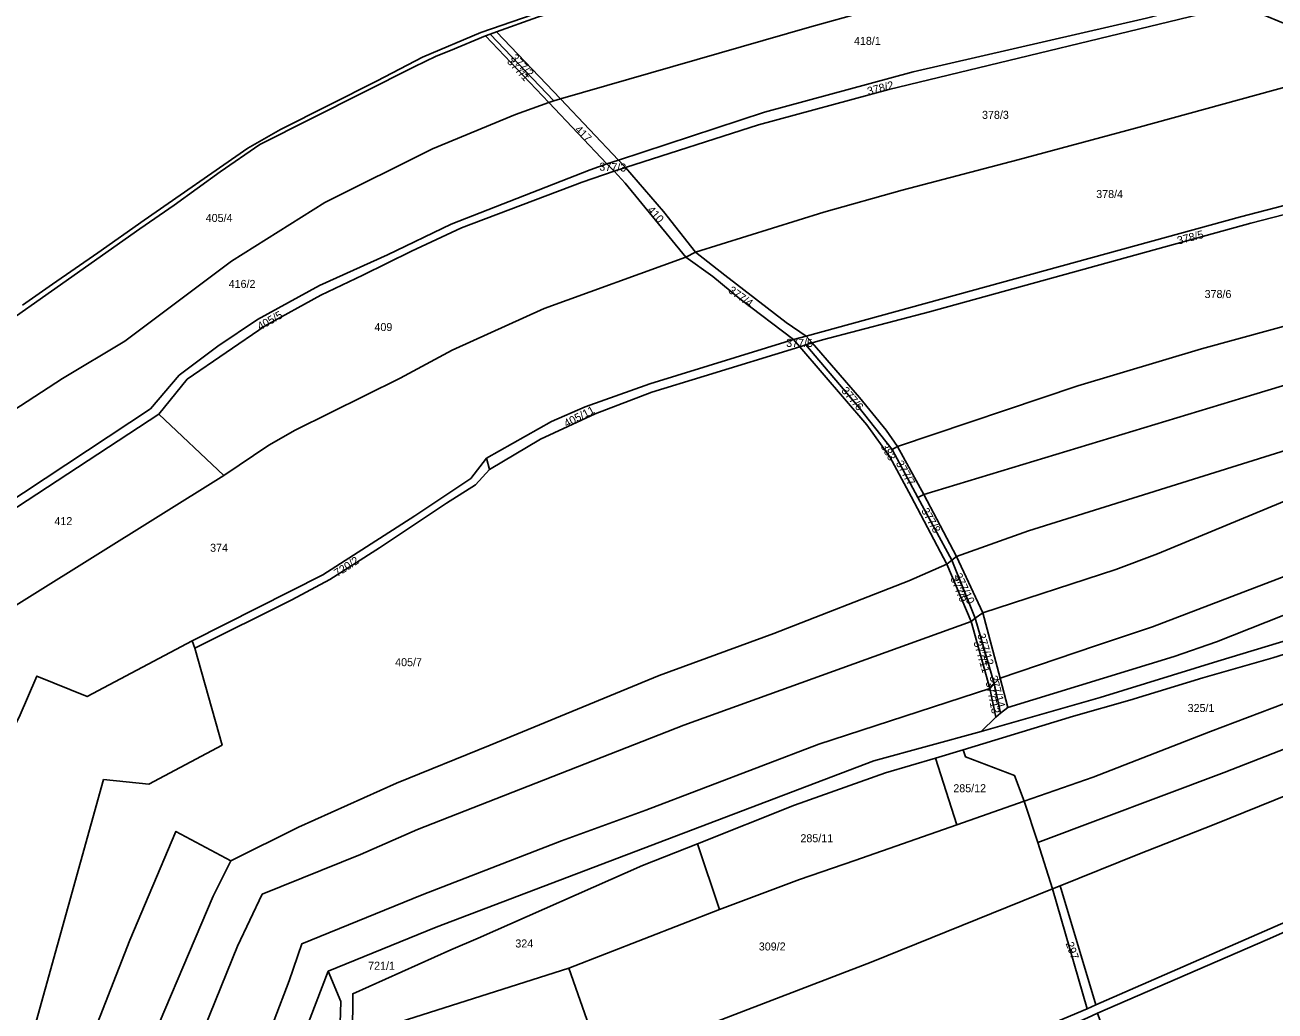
# Model space of a CAD drawing. Extents: x -629983 to -626385, y -1072828 to -1067897.
# Drawn here: x -629247.5 to -628779.1, y -1071013.1 to -1070643.4 of the extents above; entities that cross this region are included whole.
import ezdxf

# ---------------------------------------------------------------- set-up
doc = ezdxf.new("R2010")
doc.units = 0
for name, color, linetype in [('Parcela nároku', 7, 'Continuous'), ('Parcelní číslo', 7, 'Continuous'), ('Plocha PÚ', 7, 'Continuous'), ('Převzatý obvod_Ostrov', 7, 'Continuous')]:
    doc.layers.add(name, color=color, linetype=linetype)

msp = doc.modelspace()

# ---------------------------------------------------------------- linework, layer by layer
at = {"layer": 'Parcela nároku'}
for points in [[(-629013.24, -1070627.11), (-628985.46, -1070618.93), (-628958.27, -1070611.77), (-628927.76, -1070604.32), (-628897.63, -1070597.26), (-628879.21, -1070603.9), (-628844.64, -1070615.42), (-628910.36, -1070632.1), (-628953.49, -1070644.17), (-629046.78, -1070671.08), (-629070.87, -1070645.91), (-629055.42, -1070640.49)], [(-628910.36, -1070632.1), (-628844.64, -1070615.42), (-628818.36, -1070625.27), (-628798.59, -1070633.32), (-628827.25, -1070640.79), (-628914.69, -1070661.01), (-628970.38, -1070676.11), (-629025.16, -1070694.08), (-629046.78, -1070671.08), (-628953.49, -1070644.17)], [(-628798.59, -1070633.32), (-628792.54, -1070635.8), (-628923.84, -1070667.59), (-628972.69, -1070680.79), (-629022.54, -1070696.84), (-629025.16, -1070694.08), (-628970.38, -1070676.11), (-628914.69, -1070661.01), (-628827.25, -1070640.79)], [(-628972.69, -1070680.79), (-629022.54, -1070696.84), (-629008.29, -1070713.3), (-628996.19, -1070728.53), (-628948.21, -1070713.55), (-628918.79, -1070705.29), (-628875.5, -1070693.93), (-628831.39, -1070682.06), (-628740.78, -1070657.25), (-628741.75, -1070656.84), (-628792.54, -1070635.8), (-628923.84, -1070667.59)], [(-629101.65, -1070659.15), (-629093.4, -1070655.06), (-629088.1, -1070653), (-629074.99, -1070647.48), (-629051.24, -1070672.45), (-629063.68, -1070676.94), (-629094.76, -1070689.87), (-629135.11, -1070709.94), (-629170.12, -1070732.01), (-629210.07, -1070761.98), (-629233.47, -1070775.9), (-629265.09, -1070796.47), (-629274.72, -1070769.42), (-629271.88, -1070767.69), (-629254.96, -1070755.46), (-629237.53, -1070743.22), (-629204.46, -1070719.83), (-629191.61, -1070710.9), (-629174.38, -1070698.47), (-629159.54, -1070688.21)], [(-629074.99, -1070647.48), (-629073.14, -1070646.81), (-629049.29, -1070671.84), (-629051.24, -1070672.45)], [(-629046.78, -1070671.08), (-629070.87, -1070645.91), (-629073.14, -1070646.81), (-629049.29, -1070671.84)], [(-628996.19, -1070728.53), (-628948.21, -1070713.55), (-628918.79, -1070705.29), (-628875.5, -1070693.93), (-628831.39, -1070682.06), (-628740.78, -1070657.25), (-628678.53, -1070683.39), (-628715.57, -1070695.49), (-628792.01, -1070715.38), (-628954.79, -1070760.07), (-628962.29, -1070754.91), (-628985.21, -1070737.21)], [(-629025.16, -1070694.08), (-629046.78, -1070671.08), (-629049.29, -1070671.84), (-629051.24, -1070672.45), (-629029.46, -1070695.49)], [(-629094.76, -1070689.87), (-629063.68, -1070676.94), (-629051.24, -1070672.45), (-629029.46, -1070695.49), (-629035.66, -1070697.66), (-629087.84, -1070718.12), (-629111.67, -1070729.62), (-629137.1, -1070741.07), (-629160.38, -1070753.87), (-629175.26, -1070763.77), (-629189.77, -1070774.71), (-629200.54, -1070787.31), (-629255.88, -1070823.88), (-629265.09, -1070796.47), (-629233.47, -1070775.9), (-629210.07, -1070761.98), (-629170.12, -1070732.01), (-629135.11, -1070709.94)], [(-628954.79, -1070760.07), (-628792.01, -1070715.38), (-628715.57, -1070695.49), (-628678.53, -1070683.39), (-628673.98, -1070685.19), (-628698.34, -1070693.58), (-628726.09, -1070701.74), (-628788.2, -1070717.76), (-628908.59, -1070750.92), (-628948.65, -1070761.44), (-628952.57, -1070762.63)], [(-629022.54, -1070696.84), (-629025.16, -1070694.08), (-629029.46, -1070695.49), (-629026.7, -1070698.25)], [(-628682.68, -1070703.28), (-628657.28, -1070718.2), (-628720.79, -1070739.12), (-628766.88, -1070753.97), (-628806.63, -1070764.8), (-628852.98, -1070778.65), (-628920.59, -1070801.5), (-628924.83, -1070795.38), (-628934.8, -1070783.12), (-628952.57, -1070762.63), (-628948.65, -1070761.44), (-628908.59, -1070750.92), (-628788.2, -1070717.76), (-628726.09, -1070701.74), (-628698.34, -1070693.58)], [(-629186.68, -1070776.26), (-629197.39, -1070789.31), (-629173.04, -1070812.3), (-629156.13, -1070800.89), (-629146.31, -1070795.27), (-629106.88, -1070775.79), (-629087.44, -1070765.37), (-629052.94, -1070749.67), (-628999.82, -1070730.42), (-629022.57, -1070702.77), (-629026.7, -1070698.25), (-629038.74, -1070702.36), (-629083.96, -1070719.52), (-629102.68, -1070728.27), (-629120.87, -1070737.25), (-629136.63, -1070744.74), (-629157.54, -1070756.21)], [(-629008.29, -1070713.3), (-629022.54, -1070696.84), (-629026.7, -1070698.25), (-629022.57, -1070702.77), (-628999.82, -1070730.42), (-628996.19, -1070728.53)], [(-628852.98, -1070778.65), (-628806.63, -1070764.8), (-628766.88, -1070753.97), (-628720.79, -1070739.12), (-628657.28, -1070718.2), (-628621.8, -1070707.03), (-628585.37, -1070722.11), (-628616.48, -1070727.61), (-628668.51, -1070745.11), (-628714.67, -1070760.11), (-628786.96, -1070781.96), (-628910.71, -1070819.49), (-628920.59, -1070801.5)], [(-628558.83, -1070733.38), (-628585.37, -1070722.11), (-628616.48, -1070727.61), (-628668.51, -1070745.11), (-628714.67, -1070760.11), (-628786.96, -1070781.96), (-628910.71, -1070819.49), (-628898.44, -1070842.63), (-628871.48, -1070833.03), (-628737.85, -1070791.22), (-628704.59, -1070779.97), (-628653.5, -1070764.3), (-628624.58, -1070754.87), (-628588.5, -1070742.33), (-628543.99, -1070739.42)], [(-628999.82, -1070730.42), (-628996.19, -1070728.53), (-628985.21, -1070737.21), (-628962.29, -1070754.91), (-628954.79, -1070760.07), (-628959.48, -1070761.36), (-628979.67, -1070746.14), (-628989.79, -1070737.71)], [(-628871.48, -1070833.03), (-628898.44, -1070842.63), (-628888.62, -1070863.77), (-628838.74, -1070847.52), (-628823.11, -1070841.67), (-628766.75, -1070818.34), (-628648.3, -1070780.85), (-628589.41, -1070761.29), (-628565.93, -1070753.5), (-628536.65, -1070754.78), (-628495.21, -1070759.45), (-628543.99, -1070739.42), (-628588.5, -1070742.33), (-628624.58, -1070754.87), (-628653.5, -1070764.3), (-628704.59, -1070779.97), (-628737.85, -1070791.22)], [(-628952.57, -1070762.63), (-628954.79, -1070760.07), (-628959.48, -1070761.36), (-628957.18, -1070764.03), (-628954.9, -1070763.33)], [(-629050.26, -1070792.01), (-629037.59, -1070786.62), (-629013.39, -1070777.96), (-628959.48, -1070761.36), (-628957.18, -1070764.03), (-628992.94, -1070775.08), (-629012.6, -1070781.12), (-629033.87, -1070789.14), (-629054.29, -1070798.72), (-629073.48, -1070810.06), (-629074.59, -1070805.83)], [(-628935.34, -1070786.45), (-628922.49, -1070802.54), (-628912.94, -1070820.53), (-628900.23, -1070844.01), (-628902.04, -1070845.53), (-628915.37, -1070820.2), (-628923.37, -1070805.26), (-628932.03, -1070793.28), (-628957.18, -1070764.03), (-628954.9, -1070763.33)], [(-628924.83, -1070795.38), (-628934.8, -1070783.12), (-628952.57, -1070762.63), (-628954.9, -1070763.33), (-628935.34, -1070786.45), (-628922.49, -1070802.54), (-628920.59, -1070801.5)], [(-628648.3, -1070780.85), (-628589.41, -1070761.29), (-628572.41, -1070776.59), (-628625.53, -1070797.34), (-628734.06, -1070834.69), (-628769.79, -1070847.9), (-628824.99, -1070869.05), (-628846.39, -1070876.13), (-628882.09, -1070888.31), (-628888.62, -1070863.77), (-628838.74, -1070847.52), (-628823.11, -1070841.67), (-628766.75, -1070818.34)], [(-628889.23, -1070908.35), (-628883.68, -1070902.89), (-628881.9, -1070901.46), (-628879.17, -1070899.26), (-628816.86, -1070880.18), (-628801, -1070874.72), (-628763.76, -1070859.99), (-628742.31, -1070851.58), (-628735.56, -1070848.89), (-628720.22, -1070843.38), (-628564.53, -1070787.76), (-628561.86, -1070787.13), (-628551.1, -1070798.69), (-628536.84, -1070814.78), (-628534.91, -1070817.69), (-628557.5, -1070815.95), (-628585.88, -1070819.54), (-628600.88, -1070823.21), (-628678.75, -1070845.24), (-628688.76, -1070848.35), (-628744.82, -1070864.54), (-628759.63, -1070869.53), (-628800.48, -1070881.99), (-628844.62, -1070895.52)], [(-629197.39, -1070789.31), (-629173.04, -1070812.3), (-629270.52, -1070873.17), (-629303.76, -1070859.01)], [(-628910.71, -1070819.49), (-628920.59, -1070801.5), (-628922.49, -1070802.54), (-628912.94, -1070820.53)], [(-629074.59, -1070805.83), (-629073.48, -1070810.06), (-629078.63, -1070815.82), (-629089.62, -1070822.66), (-629114.65, -1070839.48), (-629133.27, -1070851.25), (-629147.58, -1070858.92), (-629183.91, -1070877.02), (-629184.9, -1070874.26), (-629135.89, -1070849.51), (-629101.48, -1070827.49), (-629080.5, -1070813.4)], [(-628898.44, -1070842.63), (-628910.71, -1070819.49), (-628912.94, -1070820.53), (-628900.23, -1070844.01)], [(-628720.36, -1070876.18), (-628702.04, -1070868.5), (-628660.34, -1070851.13), (-628626.54, -1070837.4), (-628606.71, -1070828.98), (-628587.61, -1070824.1), (-628581.08, -1070822.95), (-628556.43, -1070819.76), (-628536.2, -1070820.59), (-628538.6, -1070840.92), (-628545.57, -1070840.54), (-628558.89, -1070840.95), (-628576.35, -1070841.88), (-628601.81, -1070848.84), (-628703.02, -1070886.58), (-628798.08, -1070923.62), (-628868.01, -1070949.97), (-628873.03, -1070934.38), (-628847.27, -1070925.46), (-628803.26, -1070908.3), (-628775.51, -1070897.81), (-628747.43, -1070886.92)], [(-628854.59, -1070902.49), (-628833.46, -1070896.6), (-628806.15, -1070888.2), (-628779.89, -1070880.64), (-628727.93, -1070864.31), (-628710.91, -1070859.4), (-628691.48, -1070853.66), (-628662.34, -1070844.64), (-628606.71, -1070828.98), (-628626.54, -1070837.4), (-628660.34, -1070851.13), (-628702.04, -1070868.5), (-628720.36, -1070876.18), (-628747.43, -1070886.92), (-628775.51, -1070897.81), (-628803.26, -1070908.3), (-628847.27, -1070925.46), (-628873.03, -1070934.38), (-628876.66, -1070924.8), (-628895.1, -1070917.83), (-628895.99, -1070915.17)], [(-628900.23, -1070844.01), (-628891.44, -1070865.85), (-628892.9, -1070867.07), (-628902.04, -1070845.53)], [(-628888.62, -1070863.77), (-628898.44, -1070842.63), (-628900.23, -1070844.01), (-628891.44, -1070865.85)], [(-628891.44, -1070865.85), (-628888.62, -1070863.77), (-628882.09, -1070888.31), (-628884.28, -1070890.31)], [(-628891.44, -1070865.85), (-628884.28, -1070890.31), (-628885.99, -1070892.22), (-628892.9, -1070867.07)], [(-629243.05, -1070887.54), (-629249.69, -1070902.97), (-629259.41, -1070921.33), (-629274.51, -1070985.43), (-629284.16, -1071024.99), (-629291.51, -1071053.87), (-629257.36, -1071066.95), (-629218.07, -1070926.35), (-629201.11, -1070928.03), (-629173.63, -1070913.37), (-629183.91, -1070877.02), (-629184.9, -1070874.26), (-629224.26, -1070895.2)], [(-628884.28, -1070890.31), (-628885.99, -1070892.22), (-628883.68, -1070902.89), (-628881.9, -1070901.46)], [(-628879.17, -1070899.26), (-628882.09, -1070888.31), (-628884.28, -1070890.31), (-628881.9, -1070901.46)], [(-628876.66, -1070924.8), (-628873.03, -1070934.38), (-628898.34, -1070943.25), (-628906.36, -1070918.26), (-628895.99, -1070915.17), (-628895.1, -1070917.83)], [(-628906.36, -1070918.26), (-628898.34, -1070943.25), (-628936.49, -1070956.61), (-628957.25, -1070963.79), (-628987.23, -1070975.07), (-628995.45, -1070950.4), (-628959.11, -1070935.95), (-628925, -1070923.82)], [(-628873.03, -1070934.38), (-628898.34, -1070943.25), (-628936.49, -1070956.61), (-628957.25, -1070963.79), (-628987.23, -1070975.07), (-629043.77, -1070997.08), (-629031, -1071033.43), (-628930.4, -1070994.77), (-628862.45, -1070967.29), (-628868.01, -1070949.97)], [(-629294.85, -1071219.25), (-629303.85, -1071238.44), (-629324.52, -1071275.85), (-629358.36, -1071328.63), (-629347.5, -1071339.42), (-629338.48, -1071349.57), (-629337.96, -1071346.05), (-629294.79, -1071281.13), (-629285.17, -1071264.79), (-629267.15, -1071230.1), (-629275.62, -1071225.43), (-629262.93, -1071193.94), (-629238.65, -1071130.37), (-629229.69, -1071103.25), (-629220.42, -1071074.94), (-629206.16, -1071038.51), (-629177.01, -1070970.08), (-629170.42, -1070956.77), (-629190.93, -1070945.74), (-629208.26, -1070986.56), (-629239.55, -1071066.87), (-629258.21, -1071116.1), (-629286.97, -1071186.58), (-629300.05, -1071217.22)], [(-628987.23, -1070975.07), (-628995.45, -1070950.4), (-629016.06, -1070958.59), (-629077.67, -1070985.83), (-629087.88, -1070990.17), (-629124.71, -1071006.62), (-629124.78, -1071022.48), (-629124.32, -1071038.8), (-629121.58, -1071040.43), (-629109.7, -1071018), (-629043.77, -1070997.08)], [(-628846.18, -1071010.81), (-628859.63, -1070966.14), (-628862.45, -1070967.29), (-628849.49, -1071012.28)], [(-628862.45, -1070967.29), (-628849.49, -1071012.28), (-628903.62, -1071035.08), (-629037.57, -1071091.02), (-629063.43, -1071045.61), (-629054.12, -1071042.27), (-629031, -1071033.43), (-628930.4, -1070994.77)], [(-629129.17, -1071009.57), (-629133.86, -1070998.2), (-629145.11, -1071027.49), (-629152.33, -1071047.53), (-629166.08, -1071089.86), (-629176.77, -1071125.65), (-629162.09, -1071130.88), (-629156.06, -1071111.85), (-629148.31, -1071091.33), (-629138.68, -1071065.94), (-629130.19, -1071041.68)]]:
    msp.add_lwpolyline(points, close=True, dxfattribs=at)
for points in [[(-629033.9, -1070631.38), (-629076.7, -1070646.21), (-629098.5, -1070655.51), (-629115.52, -1070664.34), (-629151.75, -1070682.6), (-629164.05, -1070689.56), (-629202.91, -1070716.55), (-629220.25, -1070728.86), (-629237.26, -1070740.64), (-629248.44, -1070748.49)], [(-629254.96, -1070755.46), (-629237.53, -1070743.22), (-629204.46, -1070719.83), (-629191.61, -1070710.9), (-629174.38, -1070698.47), (-629159.54, -1070688.21), (-629101.65, -1070659.15), (-629093.4, -1070655.06), (-629088.1, -1070653), (-629074.99, -1070647.48), (-629073.14, -1070646.81), (-629070.87, -1070645.91), (-629055.42, -1070640.49)], [(-629255.88, -1070823.88), (-629200.54, -1070787.31), (-629189.77, -1070774.71), (-629175.26, -1070763.77), (-629160.38, -1070753.87), (-629137.1, -1070741.07), (-629111.67, -1070729.62), (-629087.84, -1070718.12), (-629035.66, -1070697.66), (-629029.46, -1070695.49), (-629026.7, -1070698.25), (-629038.74, -1070702.36), (-629083.96, -1070719.52), (-629102.68, -1070728.27), (-629120.87, -1070737.25), (-629136.63, -1070744.74), (-629157.54, -1070756.21), (-629186.68, -1070776.26), (-629197.39, -1070789.31), (-629303.76, -1070859.01)], [(-629249.69, -1070902.97), (-629243.05, -1070887.54), (-629224.26, -1070895.2), (-629184.9, -1070874.26), (-629135.89, -1070849.51), (-629101.48, -1070827.49), (-629080.5, -1070813.4), (-629074.59, -1070805.83), (-629050.26, -1070792.01), (-629037.59, -1070786.62), (-629013.39, -1070777.96), (-628959.48, -1070761.36), (-628979.67, -1070746.14), (-628989.79, -1070737.71), (-628999.82, -1070730.42), (-629052.94, -1070749.67), (-629087.44, -1070765.37), (-629106.88, -1070775.79), (-629146.31, -1070795.27), (-629156.13, -1070800.89), (-629173.04, -1070812.3), (-629270.52, -1070873.17)], [(-629257.36, -1071066.95), (-629218.07, -1070926.35), (-629201.11, -1070928.03), (-629173.63, -1070913.37), (-629183.91, -1070877.02), (-629147.58, -1070858.92), (-629133.27, -1070851.25), (-629114.65, -1070839.48), (-629089.62, -1070822.66), (-629078.63, -1070815.82), (-629073.48, -1070810.06), (-629054.29, -1070798.72), (-629033.87, -1070789.14), (-629012.6, -1070781.12), (-628992.94, -1070775.08), (-628957.18, -1070764.03), (-628932.03, -1070793.28), (-628923.37, -1070805.26), (-628915.37, -1070820.2), (-628902.04, -1070845.53), (-628916.32, -1070851.87), (-628966.93, -1070871.5), (-629009.88, -1070887.29), (-629073.22, -1070913.38), (-629108.24, -1070927.64), (-629145.08, -1070944.16), (-629170.42, -1070956.77), (-629190.93, -1070945.74), (-629208.26, -1070986.56), (-629239.55, -1071066.87)], [(-629180.38, -1071019.66), (-629167.92, -1070988.77), (-629158.6, -1070969.34), (-629121.83, -1070954.39), (-629100.42, -1070945.1), (-629056.1, -1070927.69), (-629000.6, -1070905.95), (-628892.9, -1070867.07), (-628902.04, -1070845.53), (-628916.32, -1070851.87), (-628966.93, -1070871.5), (-629009.88, -1070887.29), (-629073.22, -1070913.38), (-629108.24, -1070927.64), (-629145.08, -1070944.16), (-629170.42, -1070956.77), (-629177.01, -1070970.08), (-629206.16, -1071038.51)], [(-628763.76, -1070859.99), (-628801, -1070874.72), (-628816.86, -1070880.18), (-628879.17, -1070899.26), (-628882.09, -1070888.31), (-628846.39, -1070876.13), (-628824.99, -1070869.05), (-628769.79, -1070847.9)], [(-629165.37, -1071046.04), (-629148.53, -1071001.81), (-629143.83, -1070987.86), (-629098.68, -1070969.56), (-629046.43, -1070949.27), (-629014.84, -1070937.82), (-628950.04, -1070913.06), (-628885.99, -1070892.22), (-628892.9, -1070867.07), (-629000.6, -1070905.95), (-629056.1, -1070927.69), (-629100.42, -1070945.1), (-629121.83, -1070954.39), (-629158.6, -1070969.34), (-629167.92, -1070988.77), (-629180.38, -1071019.66)], [(-628727.93, -1070864.31), (-628779.89, -1070880.64), (-628806.15, -1070888.2), (-628833.46, -1070896.6), (-628854.59, -1070902.49), (-628895.99, -1070915.17), (-628906.36, -1070918.26), (-628925, -1070923.82), (-628959.11, -1070935.95), (-628995.45, -1070950.4), (-629016.06, -1070958.59), (-629077.67, -1070985.83), (-629087.88, -1070990.17), (-629124.71, -1071006.62), (-629124.78, -1071022.48)], [(-629252.25, -1071376.87), (-629224.56, -1071326.33), (-629205.05, -1071279.48), (-629196.24, -1071250.14), (-629182.04, -1071200.4), (-629162.09, -1071130.88), (-629156.06, -1071111.85), (-629148.31, -1071091.33), (-629138.68, -1071065.94), (-629130.19, -1071041.68), (-629129.17, -1071009.57), (-629133.86, -1070998.2), (-629093.43, -1070981.69), (-628929.4, -1070919.32), (-628889.23, -1070908.35), (-628844.62, -1070895.52), (-628800.48, -1070881.99), (-628759.63, -1070869.53)], [(-628750.94, -1070922.6), (-628801.86, -1070943.23), (-628830.51, -1070954.43), (-628859.63, -1070966.14), (-628862.45, -1070967.29), (-628868.01, -1070949.97), (-628798.08, -1070923.62), (-628703.02, -1070886.58)], [(-629165.37, -1071046.04), (-629148.53, -1071001.81), (-629143.83, -1070987.86), (-629098.68, -1070969.56), (-629046.43, -1070949.27), (-629014.84, -1070937.82), (-628950.04, -1070913.06), (-628885.99, -1070892.22), (-628883.68, -1070902.89), (-628889.23, -1070908.35), (-628929.4, -1070919.32), (-629093.43, -1070981.69), (-629133.86, -1070998.2), (-629145.11, -1071027.49)], [(-628713.88, -1070952.86), (-628846.18, -1071010.81), (-628859.63, -1070966.14), (-628830.51, -1070954.43), (-628801.86, -1070943.23), (-628750.94, -1070922.6)], [(-629274.4, -1071590.15), (-629245.72, -1071546.08), (-629230.03, -1071518.34), (-629213.07, -1071488.18), (-629210.81, -1071483.55), (-629200.66, -1071463.12), (-629192.44, -1071444.48), (-629183.39, -1071419.75), (-629168.82, -1071375.61), (-629158.55, -1071341), (-629148.56, -1071307.45), (-629142.19, -1071275.41), (-629134.38, -1071227.67), (-629126.83, -1071186.47), (-629082.5, -1071130.26), (-629060.19, -1071106.35), (-629039.95, -1071095.79), (-629036.89, -1071094.64), (-628994.87, -1071076.96), (-628959.2, -1071062.4), (-628849.35, -1071015.67), (-628845.58, -1071013.92), (-628781.86, -1070986.24), (-628696.9, -1070948.55)], [(-628713.88, -1070952.86), (-628846.18, -1071010.81), (-628849.49, -1071012.28), (-628903.62, -1071035.08), (-629037.57, -1071091.02), (-629041.47, -1071092.99), (-629063.37, -1071104.07), (-629085.5, -1071128.44), (-629130.29, -1071185.15), (-629131.09, -1071188.33), (-629148.53, -1071288.3), (-629152.61, -1071304.83), (-629162.03, -1071338.69), (-629172.05, -1071370.94), (-629181.12, -1071399.72), (-629194.61, -1071437.75), (-629202.39, -1071457.01), (-629213.81, -1071479.65), (-629215.67, -1071483.78), (-629235.4, -1071520.09), (-629248.48, -1071542.87)], [(-628696.9, -1070948.55), (-628781.86, -1070986.24), (-628845.58, -1071013.92), (-628834.01, -1071047.25), (-628829.59, -1071058.41), (-628763.6, -1071027.07)], [(-629031, -1071033.43), (-629043.77, -1070997.08), (-629109.7, -1071018)]]:
    msp.add_lwpolyline(points, dxfattribs=at)
at = {"layer": 'Plocha PÚ'}
msp.add_lwpolyline([(-629033.9, -1070631.38), (-629076.7, -1070646.21), (-629098.5, -1070655.51), (-629115.52, -1070664.34), (-629151.75, -1070682.6), (-629164.05, -1070689.56), (-629202.91, -1070716.55), (-629220.25, -1070728.86), (-629237.26, -1070740.64), (-629248.44, -1070748.49)], dxfattribs=at)
at = {"layer": 'Převzatý obvod_Ostrov'}
msp.add_lwpolyline([(-629033.9, -1070631.38), (-629076.7, -1070646.21), (-629098.5, -1070655.51), (-629115.52, -1070664.34), (-629151.75, -1070682.6), (-629164.05, -1070689.56), (-629202.91, -1070716.55), (-629220.25, -1070728.86), (-629237.26, -1070740.64), (-629248.44, -1070748.49)], dxfattribs=at)

# ---------------------------------------------------------------- texts
at = {"layer": 'Parcelní číslo'}
for s, p in [('418/1', (-628936.86, -1070650.87)), ('378/3', (-628888.87, -1070678.6)), ('378/4', (-628846.08, -1070708.29)), ('405/4', (-629179.79, -1070717.25)), ('416/2', (-629171.19, -1070741.99)), ('378/6', (-628805.46, -1070745.79)), ('409', (-629116.56, -1070758.16)), ('377/5', (-628962.26, -1070764.1)), ('412', (-629236.48, -1070830.93)), ('374', (-629178.14, -1070840.91)), ('405/7', (-629108.8, -1070883.81)), ('325/1', (-628811.83, -1070901)), ('285/12', (-628899.63, -1070931.07)), ('285/11', (-628956.93, -1070949.82)), ('324', (-629063.76, -1070989.28)), ('309/2', (-628972.52, -1070990.4)), ('721/1', (-629118.92, -1070997.62))]:
    msp.add_text(s, height=3, dxfattribs=at).set_placement(p)
for s, rotation, p in [('377/1', 312.7307, (-629067.08, -1070657.33)), ('377/2', 313.7175, (-629065.68, -1070656.01)), ('378/2', 14.654, (-628931.44, -1070669.76)), ('417', 315.2599, (-629041.73, -1070682.89)), ('377/3', 357.694, (-629032.32, -1070697.99)), ('410', 312.2737, (-629014.53, -1070712.95)), ('378/5', 14.518, (-628815.29, -1070725.73)), ('377/4', 324.26, (-628984.21, -1070743.49)), ('405/5', 29.7449, (-629159.38, -1070757.99)), ('377/6', 310.2426, (-628941.81, -1070780.63)), ('405/11', 27.4744, (-629044.59, -1070794.37)), ('383', 301.2029, (-628926.99, -1070801.38)), ('377/7', 299.6415, (-628921.29, -1070807.72)), ('377/8', 299.3727, (-628911.75, -1070825.47)), ('720/2', 33.0239, (-629130.47, -1070850.46)), ('377/10', 295.2879, (-628899.39, -1070849.76)), ('377/9', 292.543, (-628900.83, -1070850.87)), ('377/12', 286.1296, (-628890.66, -1070872.01)), ('377/11', 286.4028, (-628892.1, -1070874.84)), ('377/14', 284.9914, (-628886.1, -1070887.76)), ('377/13', 281.1173, (-628887.5, -1070889.78)), ('297', 289.9074, (-628857.57, -1070987.78))]:
    msp.add_text(s, height=3, rotation=rotation, dxfattribs=at).set_placement(p)

doc.saveas('drawing.dxf')
